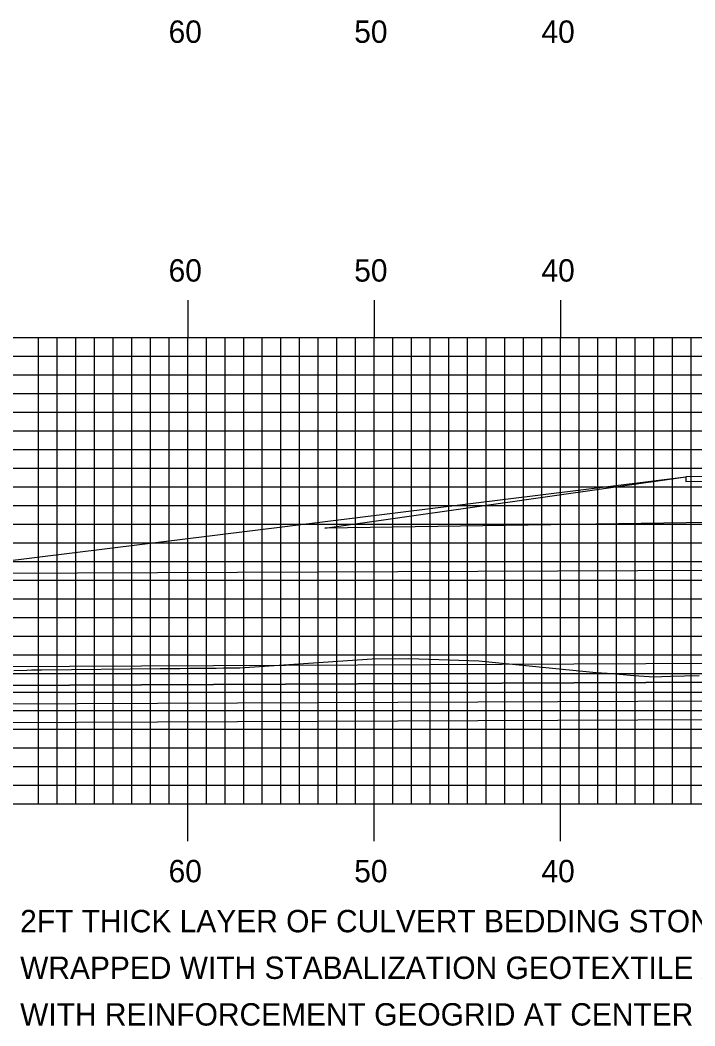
# Model space of a CAD drawing. Extents: x 1763365 to 1763708, y 442591 to 442811.
# Drawn here: x 1763461.8 to 1763498, y 442701.8 to 442755.7 of the extents above; entities that cross this region are included whole.
import ezdxf

# ---------------------------------------------------------------- set-up
doc = ezdxf.new("R2010")
doc.units = 0
for name, color, linetype in [('D_Drainage_Culvert', 7, 'Continuous'), ('D_Roadway_Edge_Shoulder', 7, 'Continuous'), ('D_Roadway_FinishedGrade', 7, 'Continuous'), ('D_Roadway_SubGrade', 7, 'Continuous'), ('D_Text_Standard', 7, 'Continuous'), ('H_V ANNOTATION', 7, 'Continuous'), ('MAJOR', 7, 'Continuous'), ('MINOR', 7, 'Continuous'), ('S_Roadway_Centerline', 7, 'Continuous')]:
    doc.layers.add(name, color=color, linetype=linetype)

msp = doc.modelspace()

# ---------------------------------------------------------------- linework, layer by layer
at = {"layer": 'D_Drainage_Culvert'}
for p, q in [((1763611.614, 442726.665), (1763443.605, 442725.949)), ((1763611.64, 442720.665), (1763443.605, 442719.949)), ((1763445.113, 442719.956), (1763610.14, 442720.663)), ((1763445.113, 442718.963), (1763610.14, 442719.67)), ((1763445.113, 442717.963), (1763610.14, 442718.67))]:
    msp.add_line(p, q, dxfattribs=at)
at = {"layer": 'D_Roadway_Edge_Shoulder'}
msp.add_lwpolyline([(1763510.88, 442731.429), (1763497.523, 442731.196), (1763497.523, 442730.946), (1763510.88, 442731.179)], close=True, dxfattribs=at)
at = {"layer": 'D_Roadway_FinishedGrade'}
for p, q in [((1763460.685, 442726.646), (1763497.523, 442731.196)), ((1763621.631, 442721.708), (1763443.605, 442720.949))]:
    msp.add_line(p, q, dxfattribs=at)
at = {"layer": 'D_Roadway_SubGrade'}
msp.add_lwpolyline([(1763497.523, 442730.946), (1763510.88, 442731.179), (1763510.88, 442730.763), (1763510.88, 442728.929), (1763478.165, 442728.449), (1763497.523, 442731.196)], close=True, dxfattribs=at)
at = {"layer": 'MAJOR'}
for p, q in [((1763470.805, 442740.669), (1763470.805, 442738.665)), ((1763480.805, 442740.669), (1763480.805, 442738.665)), ((1763490.805, 442740.669), (1763490.805, 442738.665)), ((1763390.805, 442738.665), (1763670.805, 442738.665)), ((1763390.805, 442738.665), (1763670.805, 442738.665)), ((1763470.805, 442713.665), (1763470.805, 442738.665)), ((1763480.805, 442713.665), (1763480.805, 442738.665)), ((1763490.805, 442713.665), (1763490.805, 442738.665)), ((1763390.805, 442733.665), (1763670.805, 442733.665)), ((1763390.805, 442728.665), (1763670.805, 442728.665)), ((1763390.805, 442723.665), (1763670.805, 442723.665)), ((1763390.805, 442718.665), (1763670.805, 442718.665)), ((1763390.805, 442713.665), (1763670.805, 442713.665)), ((1763390.805, 442713.665), (1763670.805, 442713.665)), ((1763470.805, 442711.661), (1763470.805, 442713.665)), ((1763480.805, 442711.661), (1763480.805, 442713.665)), ((1763490.805, 442711.661), (1763490.805, 442713.665))]:
    msp.add_line(p, q, dxfattribs=at)
at = {"layer": 'MINOR'}
for p, q in [((1763462.805, 442713.665), (1763462.805, 442738.665)), ((1763463.805, 442713.665), (1763463.805, 442738.665)), ((1763464.805, 442713.665), (1763464.805, 442738.665)), ((1763465.805, 442713.665), (1763465.805, 442738.665)), ((1763466.805, 442713.665), (1763466.805, 442738.665)), ((1763467.805, 442713.665), (1763467.805, 442738.665)), ((1763468.805, 442713.665), (1763468.805, 442738.665)), ((1763469.805, 442713.665), (1763469.805, 442738.665)), ((1763471.805, 442713.665), (1763471.805, 442738.665)), ((1763472.805, 442713.665), (1763472.805, 442738.665)), ((1763473.805, 442713.665), (1763473.805, 442738.665)), ((1763474.805, 442713.665), (1763474.805, 442738.665)), ((1763475.805, 442713.665), (1763475.805, 442738.665)), ((1763476.805, 442713.665), (1763476.805, 442738.665)), ((1763477.805, 442713.665), (1763477.805, 442738.665)), ((1763478.805, 442713.665), (1763478.805, 442738.665)), ((1763479.805, 442713.665), (1763479.805, 442738.665)), ((1763481.805, 442713.665), (1763481.805, 442738.665)), ((1763482.805, 442713.665), (1763482.805, 442738.665)), ((1763483.805, 442713.665), (1763483.805, 442738.665)), ((1763484.805, 442713.665), (1763484.805, 442738.665)), ((1763485.805, 442713.665), (1763485.805, 442738.665)), ((1763486.805, 442713.665), (1763486.805, 442738.665)), ((1763487.805, 442713.665), (1763487.805, 442738.665)), ((1763488.805, 442713.665), (1763488.805, 442738.665)), ((1763489.805, 442713.665), (1763489.805, 442738.665)), ((1763491.805, 442713.665), (1763491.805, 442738.665)), ((1763492.805, 442713.665), (1763492.805, 442738.665)), ((1763493.805, 442713.665), (1763493.805, 442738.665)), ((1763494.805, 442713.665), (1763494.805, 442738.665)), ((1763495.805, 442713.665), (1763495.805, 442738.665)), ((1763496.805, 442713.665), (1763496.805, 442738.665)), ((1763497.805, 442713.665), (1763497.805, 442738.665)), ((1763390.805, 442737.665), (1763670.805, 442737.665)), ((1763390.805, 442736.665), (1763670.805, 442736.665)), ((1763390.805, 442735.665), (1763670.805, 442735.665)), ((1763390.805, 442734.665), (1763670.805, 442734.665)), ((1763390.805, 442732.665), (1763670.805, 442732.665)), ((1763390.805, 442731.665), (1763670.805, 442731.665)), ((1763390.805, 442730.665), (1763670.805, 442730.665)), ((1763390.805, 442729.665), (1763670.805, 442729.665)), ((1763390.805, 442727.665), (1763670.805, 442727.665)), ((1763390.805, 442726.665), (1763670.805, 442726.665)), ((1763390.805, 442725.665), (1763670.805, 442725.665)), ((1763390.805, 442724.665), (1763670.805, 442724.665)), ((1763390.805, 442722.665), (1763670.805, 442722.665)), ((1763390.805, 442721.665), (1763670.805, 442721.665)), ((1763390.805, 442720.665), (1763670.805, 442720.665)), ((1763390.805, 442720.665), (1763670.805, 442720.665)), ((1763390.805, 442719.665), (1763670.805, 442719.665)), ((1763390.805, 442717.665), (1763670.805, 442717.665)), ((1763390.805, 442716.665), (1763670.805, 442716.665)), ((1763390.805, 442715.665), (1763670.805, 442715.665)), ((1763390.805, 442714.665), (1763670.805, 442714.665))]:
    msp.add_line(p, q, dxfattribs=at)
at = {"layer": 'S_Roadway_Centerline'}
msp.add_lwpolyline([(1763461.47, 442720.82), (1763462.177, 442720.843), (1763462.432, 442720.847), (1763462.702, 442720.851), (1763462.984, 442720.854), (1763469.333, 442720.919), (1763469.861, 442720.925), (1763470.387, 442720.93), (1763470.903, 442720.935), (1763471.878, 442720.944), (1763472.322, 442720.948), (1763472.729, 442720.952), (1763473.152, 442720.957), (1763473.607, 442720.962), (1763480.697, 442721.435), (1763482.66, 442721.468), (1763486.412, 442721.344), (1763492.72, 442720.715), (1763493.304, 442720.667), (1763493.971, 442720.614), (1763494.724, 442720.556), (1763495.557, 442720.496), (1763495.766, 442720.482), (1763496.706, 442720.512), (1763497.456, 442720.534), (1763498.231, 442720.555)], dxfattribs=at)

# ---------------------------------------------------------------- texts
at = {"layer": 'D_Text_Standard'}
for s, p in [('2FT THICK LAYER OF CULVERT BEDDING STONE', (1763461.816, 442706.784)), ('WRAPPED WITH STABALIZATION GEOTEXTILE AND', (1763461.816, 442704.284)), ('WITH REINFORCEMENT GEOGRID AT CENTER', (1763461.816, 442701.784))]:
    msp.add_text(s, height=1.2, dxfattribs=at).set_placement(p)
at = {"layer": 'H_V ANNOTATION'}
for s, p in [('60', (1763469.778, 442754.465)), ('50', (1763479.735, 442754.465)), ('40', (1763489.778, 442754.465)), ('60', (1763469.778, 442741.665)), ('50', (1763479.735, 442741.665)), ('40', (1763489.778, 442741.665)), ('60', (1763469.778, 442709.465)), ('50', (1763479.735, 442709.465)), ('40', (1763489.778, 442709.465))]:
    msp.add_text(s, height=1.2, dxfattribs=at).set_placement(p)

doc.saveas('drawing.dxf')
